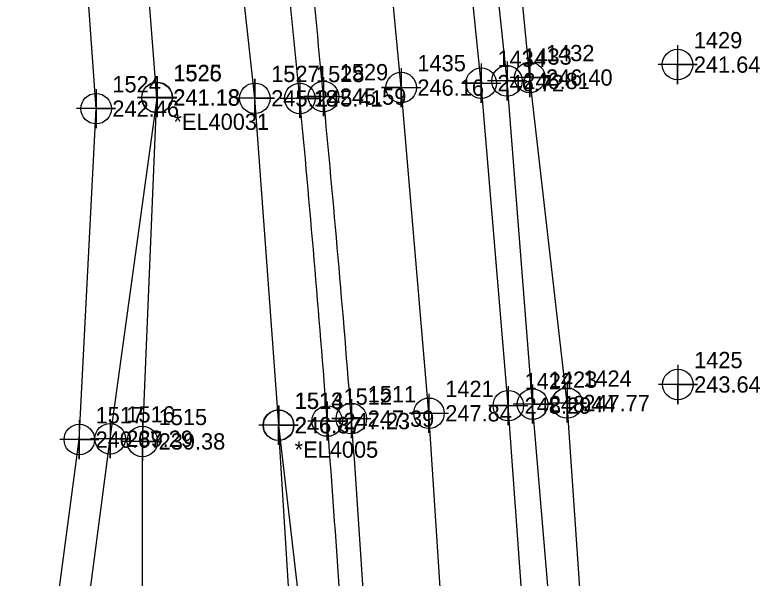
# Model space of a CAD drawing. Extents: x 2130962 to 2131465, y 643052 to 644206.
# Drawn here: x 2131170.6 to 2131285, y 643392.7 to 643479.2 of the extents above; entities that cross this region are included whole.
import ezdxf

# ---------------------------------------------------------------- set-up
doc = ezdxf.new("R2010")
doc.units = 0
for name, color, linetype in [('Exist DTM Breakline', 7, 'Continuous'), ('Exist DTM Breakline Cogo Comment', 7, 'Continuous'), ('Exist DTM Breakline Cogo Elevation', 7, 'Continuous'), ('Exist DTM Breakline Cogo Number', 7, 'Continuous'), ('Exist DTM Breakline Cogo Point CELL', 7, 'Continuous'), ('Exist DTM Drainline', 7, 'Continuous'), ('Exist DTM Drainline Cogo Comment', 7, 'Continuous'), ('Exist DTM Drainline Cogo Elevation', 7, 'Continuous'), ('Exist DTM Drainline Cogo Number', 7, 'Continuous'), ('Exist DTM Drainline Cogo Point CELL', 7, 'Continuous'), ('Exist DTM Regular Point CELL', 7, 'Continuous'), ('Exist DTM Regular Point Cogo Elevation', 7, 'Continuous'), ('Exist DTM Regular Point Cogo Number', 7, 'Continuous'), ('Exist Roads EOP', 7, 'Continuous'), ('Exist Roads EOP Cogo Elevation', 7, 'Continuous'), ('Exist Roads EOP Cogo Number', 7, 'Continuous'), ('Exist Roads EOP Cogo Point CELL', 7, 'Continuous'), ('Exist Roads EOT', 7, 'Continuous'), ('Exist Roads EOT Cogo Elevation', 7, 'Continuous'), ('Exist Roads EOT Cogo Number', 7, 'Continuous'), ('Exist Roads EOT Cogo Point CELL', 7, 'Continuous'), ('Exist Roads Soil', 7, 'Continuous'), ('Exist Roads Soil Cogo Elevation', 7, 'Continuous'), ('Exist Roads Soil Cogo Number', 7, 'Continuous'), ('Exist Roads Soil Cogo Point CELL', 7, 'Continuous')]:
    doc.layers.add(name, color=color, linetype=linetype)

msp = doc.modelspace()

# ---------------------------------------------------------------- linework, layer by layer
at = {"layer": 'Exist DTM Breakline'}
for points in [[(2131266.3306, 643269.372), (2131264.0776, 643319.4437), (2131258.8396, 643369.5498), (2131255.3671, 643419.5794), (2131249.6414, 643469.556), (2131244.7652, 643520.0623), (2131238.8778, 643569.4077), (2131228.6495, 643620.6699), (2131219.85, 643669.4823), (2131206.9682, 643717.8453), (2131195.8132, 643768.1497), (2131183.2404, 643816.8151), (2131169.0496, 643865.1461), (2131151.2314, 643913.4424), (2131130.7295, 643958.9736), (2131122.7411, 643983.0115)], [(2131000.7408, 643235.0731), (2131050.2503, 643235.0771), (2131099.3971, 643233.3967), (2131102.4734, 643233.467), (2131117.9784, 643240.6457), (2131141.4902, 643260.2289), (2131148.9668, 643267.309), (2131161.3925, 643274.3195), (2131169.1458, 643283.2692), (2131172.0772, 643292.493), (2131174.434, 643316.7319), (2131174.0607, 643347.0813), (2131174.2633, 643367.3367), (2131180.4607, 643413.966), (2131183.0424, 643464.7744), (2131179.7562, 643510.5479), (2131157.5016, 643561.2065), (2131139.0887, 643604.6918), (2131124.996, 643650.6897)], [(2131000.2707, 643222.2884), (2131049.3172, 643219.2511), (2131099.5024, 643216.1866), (2131123.0232, 643217.8518), (2131146.7721, 643223.5416), (2131166.8509, 643229.4959), (2131199.4918, 643255.6512), (2131208.4065, 643272.9132), (2131217.3052, 643317.6851), (2131214.0619, 643367.4973), (2131211.0353, 643416.1836)]]:
    msp.add_lwpolyline(points, dxfattribs=at)
at = {"layer": 'Exist DTM Breakline Cogo Point CELL'}
for points in [[(2131249.6414, 643472.556), (2131249.6414, 643466.556), (2131249.6414, 643469.556), (2131252.6414, 643469.556), (2131246.6414, 643469.556)], [(2131183.0424, 643467.7744), (2131183.0424, 643461.7744), (2131183.0424, 643464.7744), (2131186.0424, 643464.7744), (2131180.0424, 643464.7744)], [(2131255.3671, 643422.5794), (2131255.3671, 643416.5794), (2131255.3671, 643419.5794), (2131258.3671, 643419.5794), (2131252.3671, 643419.5794)], [(2131211.0353, 643419.1836), (2131211.0353, 643413.1836), (2131211.0353, 643416.1836), (2131214.0353, 643416.1836), (2131208.0353, 643416.1836)], [(2131180.4607, 643416.966), (2131180.4607, 643410.966), (2131180.4607, 643413.966), (2131183.4607, 643413.966), (2131177.4607, 643413.966)]]:
    msp.add_lwpolyline(points, dxfattribs=at)
for centre in [(2131249.6414, 643469.556), (2131183.0424, 643464.7744), (2131255.3671, 643419.5794), (2131211.0353, 643416.1836), (2131180.4607, 643413.966)]:
    msp.add_circle(centre, 2.344, dxfattribs=at)
at = {"layer": 'Exist DTM Drainline'}
for points in [[(2131000.2029, 643226.7228), (2131050.9884, 643228.9032), (2131099.0297, 643228.5605), (2131120.2968, 643239.3591), (2131144.9156, 643253.3469), (2131146.4739, 643252.3674), (2131154.3188, 643256.8046), (2131168.9618, 643265.5132), (2131176.6257, 643272.964), (2131179.8144, 643285.303), (2131183.3842, 643315.022), (2131190.1471, 643365.8731), (2131190.1489, 643413.686), (2131192.3886, 643466.4632), (2131188.8083, 643512.615), (2131184.0059, 643563.7066), (2131175.3, 643610.7482), (2131168.3784, 643658.7431), (2131156.7476, 643707.4708), (2131144.9036, 643754.0458), (2131132.9438, 643802.544), (2131118.0831, 643847.9475), (2131104.0084, 643896.8663), (2131096.3866, 643919.4077)], [(2131149.8388, 643262.7067), (2131163.2746, 643268.7404), (2131165.1512, 643269.4553), (2131171.0778, 643276.7299), (2131176.4073, 643288.8357), (2131178.5355, 643315.9841), (2131178.9558, 643366.5567), (2131185.1892, 643414.0962), (2131192.3516, 643466.0067)]]:
    msp.add_lwpolyline(points, dxfattribs=at)
at = {"layer": 'Exist DTM Drainline Cogo Point CELL'}
for points in [[(2131192.3886, 643469.4632), (2131192.3886, 643463.4632), (2131192.3886, 643466.4632), (2131195.3886, 643466.4632), (2131189.3886, 643466.4632)], [(2131192.4211, 643469.5107), (2131192.4211, 643463.5107), (2131192.4211, 643466.5107), (2131195.4211, 643466.5107), (2131189.4211, 643466.5107)], [(2131185.1892, 643417.0962), (2131185.1892, 643411.0962), (2131185.1892, 643414.0962), (2131188.1892, 643414.0962), (2131182.1892, 643414.0962)], [(2131190.1489, 643416.686), (2131190.1489, 643410.686), (2131190.1489, 643413.686), (2131193.1489, 643413.686), (2131187.1489, 643413.686)]]:
    msp.add_lwpolyline(points, dxfattribs=at)
for centre in [(2131192.3886, 643466.4632), (2131192.4211, 643466.5107), (2131185.1892, 643414.0962), (2131190.1489, 643413.686)]:
    msp.add_circle(centre, 2.344, dxfattribs=at)
at = {"layer": 'Exist DTM Regular Point CELL'}
for points in [[(2131272.3452, 643474.5405), (2131272.3452, 643468.5405), (2131272.3452, 643471.5405), (2131275.3452, 643471.5405), (2131269.3452, 643471.5405)], [(2131272.3948, 643425.4298), (2131272.3948, 643419.4298), (2131272.3948, 643422.4298), (2131275.3948, 643422.4298), (2131269.3948, 643422.4298)]]:
    msp.add_lwpolyline(points, dxfattribs=at)
for centre in [(2131272.3452, 643471.5405), (2131272.3948, 643422.4298)]:
    msp.add_circle(centre, 2.344, dxfattribs=at)
at = {"layer": 'Exist Roads EOP'}
msp.add_lwpolyline([(2131264.2715, 643222.5647), (2131259.8757, 643269.3254), (2131257.0196, 643319.4043), (2131254.2561, 643369.6499), (2131250.0777, 643419.4187), (2131246.1511, 643469.0294), (2131240.8382, 643519.1271), (2131234.3674, 643568.5584), (2131226.3321, 643620.1808), (2131217.0271, 643668.7116), (2131205.6213, 643717.607), (2131192.0578, 643767.2595), (2131177.9714, 643815.0911), (2131162.2913, 643862.9344), (2131145.3604, 643910.8486), (2131126.9113, 643957.2915), (2131112.3691, 643996.1228)], dxfattribs=at)
msp.add_spline([(2131166.2495, 643216.6951), (2131171.8131, 643218.7244), (2131182.3713, 643223.9726), (2131191.8117, 643231.1489), (2131200.5013, 643239.6993), (2131208.8071, 643249.0697), (2131216.0672, 643259.0032), (2131218.7188, 643264.347), (2131220.5363, 643270.0958), (2131222.8445, 643282.0077), (2131224.3583, 643293.9245), (2131224.8763, 643317.7904), (2131222.0632, 643367.6716), (2131218.5448, 643416.8114), (2131214.3187, 643466.3462), (2131209.1735, 643515.6666), (2131202.7939, 643565.1545), (2131195.0475, 643613.9937), (2131186.4014, 643662.4763), (2131176.0113, 643711.405), (2131164.6154, 643759.8896), (2131151.874, 643807.8526), (2131137.8554, 643855.4065), (2131122.5733, 643902.8574), (2131105.9622, 643949.4862), (2131091.5349, 643988.0437)], degree=3, dxfattribs=at)
at = {"layer": 'Exist Roads EOP Cogo Point CELL'}
for points in [[(2131246.1511, 643472.0294), (2131246.1511, 643466.0294), (2131246.1511, 643469.0294), (2131249.1511, 643469.0294), (2131243.1511, 643469.0294)], [(2131214.3187, 643469.3462), (2131214.3187, 643463.3462), (2131214.3187, 643466.3462), (2131217.3187, 643466.3462), (2131211.3187, 643466.3462)], [(2131250.0777, 643422.4187), (2131250.0777, 643416.4187), (2131250.0777, 643419.4187), (2131253.0777, 643419.4187), (2131247.0777, 643419.4187)], [(2131218.5448, 643419.8114), (2131218.5448, 643413.8114), (2131218.5448, 643416.8114), (2131221.5448, 643416.8114), (2131215.5448, 643416.8114)]]:
    msp.add_lwpolyline(points, dxfattribs=at)
for centre in [(2131246.1511, 643469.0294), (2131214.3187, 643466.3462), (2131250.0777, 643419.4187), (2131218.5448, 643416.8114)]:
    msp.add_circle(centre, 2.344, dxfattribs=at)
at = {"layer": 'Exist Roads EOT'}
for points in [[(2131255.7894, 643269.2666), (2131252.7511, 643319.2443), (2131249.9083, 643369.5477), (2131246.3502, 643419.1778), (2131242.1933, 643468.6938), (2131237.0867, 643518.9193), (2131230.8671, 643568.2588), (2131222.7066, 643619.1047), (2131213.6442, 643668.3078), (2131202.755, 643717.0933), (2131189.234, 643766.4577), (2131174.9499, 643814.1787), (2131159.2111, 643861.933), (2131141.9103, 643909.6722), (2131123.7008, 643956.0828), (2131104.9436, 644003.1503), (2131086.2706, 644048.8072), (2131065.6997, 644094.9191), (2131044.3618, 644140.0645), (2131021.6804, 644185.4526)], [(2131237.6994, 643363.706), (2131234.1644, 643418.0043), (2131229.8934, 643468.0098), (2131225.1139, 643518.3873), (2131218.7748, 643566.6133), (2131210.7043, 643617.3811), (2131201.4139, 643666.7928), (2131191.4121, 643714.0755), (2131179.6696, 643764.3904), (2131167.3006, 643812.1237), (2131153.7359, 643860.4033), (2131138.3711, 643908.8544), (2131125.1607, 643951.4161)]]:
    msp.add_lwpolyline(points, dxfattribs=at)
msp.add_spline([(2131166.718, 643215.2083), (2131172.3866, 643217.1804), (2131211.4056, 643247.1499), (2131223.758, 643268.7314), (2131228.3848, 643317.935), (2131225.533, 643367.8628), (2131222.2486, 643417.1873), (2131217.9619, 643466.6275), (2131212.8794, 643516.2377), (2131206.5633, 643565.5764), (2131198.9021, 643614.6757), (2131189.6851, 643663.4055), (2131179.3985, 643712.1311), (2131168.3085, 643760.7185), (2131155.755, 643808.9129), (2131141.6748, 643856.5528), (2131126.5354, 643904.2758), (2131110.3559, 643951.0191), (2131092.4533, 643998.1348), (2131073.722, 644043.631), (2131053.1654, 644089.359), (2131032.0052, 644134.0908), (2131009.0644, 644179.3802)], degree=3, dxfattribs=at)
at = {"layer": 'Exist Roads EOT Cogo Point CELL'}
for points in [[(2131242.1933, 643471.6938), (2131242.1933, 643465.6938), (2131242.1933, 643468.6938), (2131239.1933, 643468.6938), (2131245.1933, 643468.6938)], [(2131229.8934, 643471.0098), (2131229.8934, 643465.0098), (2131229.8934, 643468.0098), (2131226.8934, 643468.0098), (2131232.8934, 643468.0098)], [(2131217.9619, 643469.6275), (2131217.9619, 643463.6275), (2131217.9619, 643466.6275), (2131214.9619, 643466.6275), (2131220.9619, 643466.6275)], [(2131246.3502, 643422.1778), (2131246.3502, 643416.1778), (2131246.3502, 643419.1778), (2131243.3502, 643419.1778), (2131249.3502, 643419.1778)], [(2131222.2486, 643420.1873), (2131222.2486, 643414.1873), (2131222.2486, 643417.1873), (2131219.2486, 643417.1873), (2131225.2486, 643417.1873)], [(2131234.1644, 643421.0043), (2131234.1644, 643415.0043), (2131234.1644, 643418.0043), (2131231.1644, 643418.0043), (2131237.1644, 643418.0043)]]:
    msp.add_lwpolyline(points, dxfattribs=at)
for centre in [(2131242.1933, 643468.6938), (2131229.8934, 643468.0098), (2131217.9619, 643466.6275), (2131246.3502, 643419.1778), (2131234.1644, 643418.0043), (2131222.2486, 643417.1873)]:
    msp.add_circle(centre, 2.344, dxfattribs=at)
at = {"layer": 'Exist Roads Soil'}
msp.add_lwpolyline([(2131224.8674, 643317.753), (2131220.141, 643317.6487), (2131216.7544, 643367.544), (2131211.084, 643416.163), (2131207.4344, 643466.363), (2131202.1097, 643514.7948), (2131195.0195, 643564.3052), (2131187.2605, 643612.6498), (2131179.506, 643660.9545), (2131164.8317, 643709.0781), (2131153.9175, 643755.9834), (2131140.8896, 643804.492), (2131127.2512, 643851.9231), (2131113.4771, 643899.8082), (2131083.6685, 643994.997), (2131066.191, 644040.9476), (2131049.1539, 644087.3869)], dxfattribs=at)
at = {"layer": 'Exist Roads Soil Cogo Point CELL'}
for points in [[(2131207.4344, 643463.363), (2131207.4344, 643469.363), (2131207.4344, 643466.363), (2131210.4344, 643466.363), (2131204.4344, 643466.363)], [(2131211.084, 643413.163), (2131211.084, 643419.163), (2131211.084, 643416.163), (2131214.084, 643416.163), (2131208.084, 643416.163)]]:
    msp.add_lwpolyline(points, dxfattribs=at)
for centre in [(2131207.4344, 643466.363), (2131211.084, 643416.163)]:
    msp.add_circle(centre, 2.344, dxfattribs=at)

# ---------------------------------------------------------------- texts
at = {"layer": 'Exist DTM Breakline Cogo Comment'}
msp.add_text('*EL4005', height=2.5, dxfattribs=at).set_placement((2131213.5353, 643411.1836))
at = {"layer": 'Exist DTM Breakline Cogo Elevation'}
for s, p in [('246.40', (2131252.1414, 643468.306)), ('242.46', (2131185.5424, 643463.5244)), ('247.77', (2131257.8671, 643418.3294)), ('246.87', (2131213.5353, 643414.9336)), ('240.67', (2131182.9607, 643412.716))]:
    msp.add_text(s, height=2.5, dxfattribs=at).set_placement(p)
at = {"layer": 'Exist DTM Breakline Cogo Number'}
for s, p in [('1432', (2131252.1414, 643472.056)), ('1524', (2131185.5424, 643467.2744)), ('1424', (2131257.8671, 643422.0794)), ('1513', (2131213.5353, 643418.6836)), ('1517', (2131182.9607, 643416.466))]:
    msp.add_text(s, height=2.5, dxfattribs=at).set_placement(p)
at = {"layer": 'Exist DTM Drainline Cogo Comment'}
msp.add_text('*EL40031', height=2.5, dxfattribs=at).set_placement((2131194.9211, 643461.5107))
at = {"layer": 'Exist DTM Drainline Cogo Elevation'}
for s, p in [('241.18', (2131194.8886, 643465.2132)), ('241.18', (2131194.9211, 643465.2607)), ('239.29', (2131187.6892, 643412.8462)), ('239.38', (2131192.6489, 643412.436))]:
    msp.add_text(s, height=2.5, dxfattribs=at).set_placement(p)
at = {"layer": 'Exist DTM Drainline Cogo Number'}
for s, p in [('1526', (2131194.8886, 643468.9632)), ('1525', (2131194.9211, 643469.0107)), ('1516', (2131187.6892, 643416.5962)), ('1515', (2131192.6489, 643416.186))]:
    msp.add_text(s, height=2.5, dxfattribs=at).set_placement(p)
at = {"layer": 'Exist DTM Regular Point Cogo Elevation'}
for s, p in [('241.64', (2131274.8452, 643470.2905)), ('243.64', (2131274.8948, 643421.1798))]:
    msp.add_text(s, height=2.5, dxfattribs=at).set_placement(p)
at = {"layer": 'Exist DTM Regular Point Cogo Number'}
for s, p in [('1429', (2131274.8452, 643474.0405)), ('1425', (2131274.8948, 643424.9298))]:
    msp.add_text(s, height=2.5, dxfattribs=at).set_placement(p)
at = {"layer": 'Exist Roads EOP Cogo Elevation'}
for s, p in [('246.81', (2131248.6511, 643467.7794)), ('245.41', (2131216.8187, 643465.0962)), ('248.44', (2131252.5777, 643418.1687)), ('247.23', (2131221.0448, 643415.5614))]:
    msp.add_text(s, height=2.5, dxfattribs=at).set_placement(p)
at = {"layer": 'Exist Roads EOP Cogo Number'}
for s, p in [('1433', (2131248.6511, 643471.5294)), ('1528', (2131216.8187, 643468.8462)), ('1423', (2131252.5777, 643421.9187)), ('1512', (2131221.0448, 643419.3114))]:
    msp.add_text(s, height=2.5, dxfattribs=at).set_placement(p)
at = {"layer": 'Exist Roads EOT Cogo Elevation'}
for s, p in [('246.72', (2131244.6933, 643467.4438)), ('246.16', (2131232.3934, 643466.7598)), ('245.59', (2131220.4619, 643465.3775)), ('248.29', (2131248.8502, 643417.9278)), ('247.84', (2131236.6644, 643416.7543)), ('247.39', (2131224.7486, 643415.9373))]:
    msp.add_text(s, height=2.5, dxfattribs=at).set_placement(p)
at = {"layer": 'Exist Roads EOT Cogo Number'}
for s, p in [('1435', (2131232.3934, 643470.5098)), ('1434', (2131244.6933, 643471.1938)), ('1529', (2131220.4619, 643469.1275)), ('1422', (2131248.8502, 643421.6778)), ('1421', (2131236.6644, 643420.5043)), ('1511', (2131224.7486, 643419.6873))]:
    msp.add_text(s, height=2.5, dxfattribs=at).set_placement(p)
at = {"layer": 'Exist Roads Soil Cogo Elevation'}
for s, p in [('245.18', (2131209.9344, 643465.113)), ('246.87', (2131213.584, 643414.913))]:
    msp.add_text(s, height=2.5, dxfattribs=at).set_placement(p)
at = {"layer": 'Exist Roads Soil Cogo Number'}
for s, p in [('1527', (2131209.9344, 643468.863)), ('1514', (2131213.584, 643418.663))]:
    msp.add_text(s, height=2.5, dxfattribs=at).set_placement(p)

doc.saveas('drawing.dxf')
